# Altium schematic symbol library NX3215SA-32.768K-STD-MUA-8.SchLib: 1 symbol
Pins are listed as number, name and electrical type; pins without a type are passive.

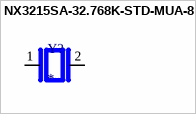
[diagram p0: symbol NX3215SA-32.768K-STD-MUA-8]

## NX3215SA-32.768K-STD-MUA-8
designator Y?
32.768 kHz Â±20ppm Crystal 12.5pF 70 kOhms 2-SMD, No Lead; MF: NDK America,; MP: NX3215SA-32.768K-STD-MUA-8
footprint XTAL_NX3215SA-32.768K-STD-MUA-8
pins: 1, 2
